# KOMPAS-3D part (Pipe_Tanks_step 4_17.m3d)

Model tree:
1. X Axis
2. Y Axis
3. Z Axis  (labels: Pipe Dn 20; Valve Dy 50)
     Òîëùèíà ñòåíêè 1 = 1

Referenced files in C:\Documents and Settings\kashirsky\Мои документы\Camtasia Studio\Pipelines3D\Tanks\: Tanks_step 4.a3d
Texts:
  Pipe Dn 50
  Steel ASTM A295
  Three Point Plane
  Plane at Angle
  Line and Point Plane
  Axis through Two Vertices
  Axis of Feature
  Axis of Conical Surface
  Axis through Edge
  Trim by Surface
  Trim by Sketch
  Feature with No History
  Intersection Axis of Two Planes
  Two Line Plane
  Line and Face Plane
  Bend by line
  Hole in sheet body
  Cut in sheet body
  Point in CM
  Linear Dimension from Line to Point
  Surface Finish Symbol
  Geometric Tolerance Symbol
  Leader #1
  Leader #2
  Leader #3
  Shape Deviations and Datum
  Node point number
  Mark of coordination axis
  Node point designation
  Mark/Reference designation with leader
  Mark/reference designation on line
  Mark/Reference designation without leader
  Pipe Dn 20
  Valve Dy 50
  Plane of section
